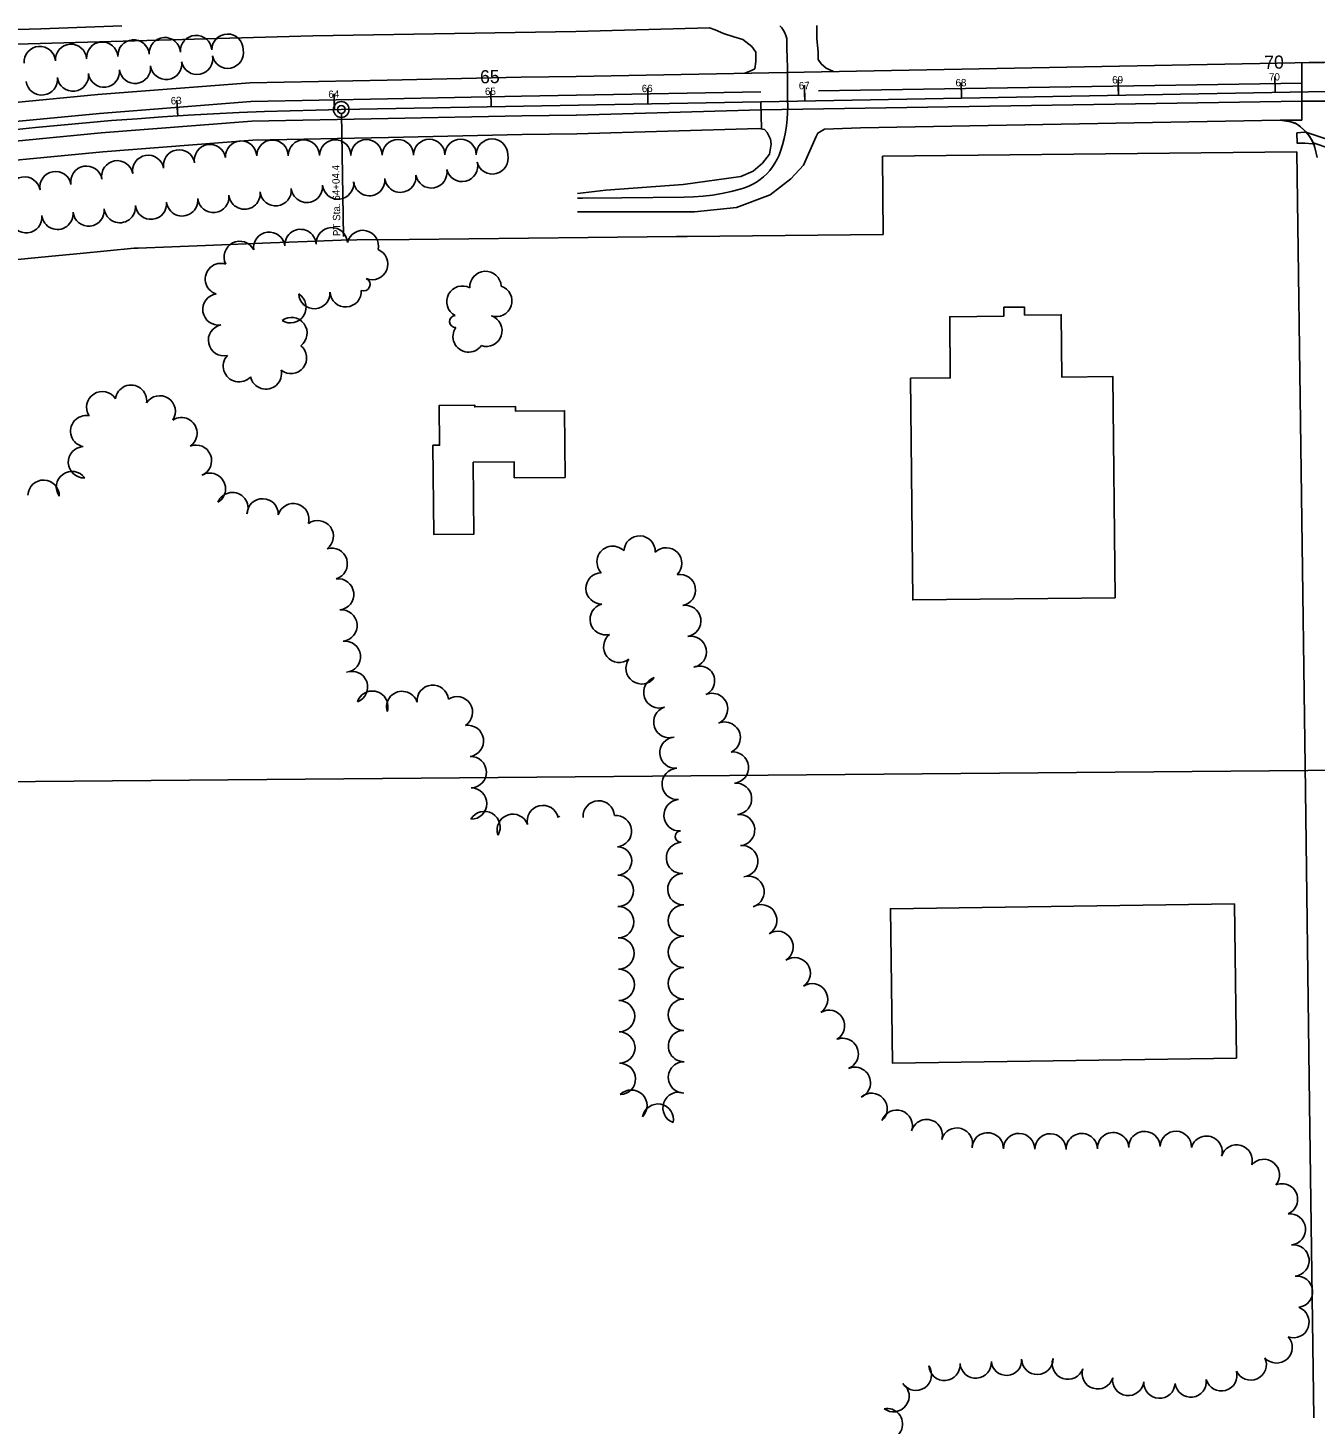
# Model space of a CAD drawing. Extents: x -2233 to 187241, y 4582 to 150524.
# Drawn here: x 106148 to 106969, y 58600 to 59491 of the extents above; entities that cross this region are included whole.
import ezdxf

# ---------------------------------------------------------------- set-up
doc = ezdxf.new("R2010")
doc.units = 0
for name, color, linetype in [('AP_X_Misc', 7, 'Continuous'), ('BLDG', 7, 'Continuous'), ('GE_X_CL_100', 7, 'Continuous'), ('GE_X_CL_20', 7, 'Continuous'), ('GE_X_CL_2000', 7, 'Continuous'), ('GE_X_CL_50', 7, 'Continuous'), ('GRID', 7, 'Continuous'), ('PM_P_CL_Double_Solid', 7, 'Continuous'), ('PM_P_Crosswalk', 7, 'Continuous'), ('PM_P_Edge_Line', 7, 'Continuous'), ('PM_P_Lane_Line', 7, 'Continuous'), ('PM_P_Text', 7, 'Continuous'), ('PV_P_Curb_Ramp', 7, 'Continuous'), ('ROAD', 7, 'Continuous'), ('RW_X_Fee_RW', 7, 'Continuous'), ('SC_Scratch2', 7, 'Continuous'), ('TREES', 7, 'Continuous')]:
    doc.layers.add(name, color=color, linetype=linetype)

msp = doc.modelspace()

# ---------------------------------------------------------------- linework, layer by layer
at = {"layer": 'AP_X_Misc'}
for p, q in [((106960.12, 59431.73), (106960.11, 59468.34)), ((106946.44, 59431.71), (106960.12, 59431.73))]:
    msp.add_line(p, q, dxfattribs=at)
at = {"layer": 'BLDG'}
for points in [[(106841.13, 59127.15), (106839.71, 59268.23), (106807.13, 59267.9), (106806.73, 59307.67), (106783.38, 59307.43), (106783.32, 59312.55), (106770.16, 59312.42), (106770.22, 59306.75), (106735.64, 59306.4), (106736.03, 59267.4), (106710.64, 59267.14), (106712.07, 59125.86)], [(106457.94, 59203.65), (106457.85, 59213.86), (106431.86, 59213.63), (106432.26, 59167.76), (106406.63, 59167.53), (106406.14, 59224.38), (106410.39, 59224.42), (106410.16, 59249.8), (106432.8, 59249.99), (106432.81, 59248.83), (106458.69, 59249.06), (106458.72, 59246.21), (106490.02, 59246.48), (106490.39, 59203.93)], [(106918.55, 58833.53), (106699.14, 58830.47), (106697.78, 58928.9), (106917.18, 58931.96)]]:
    msp.add_lwpolyline(points, close=True, dxfattribs=at)
at = {"layer": 'GE_X_CL_100'}
for p, q in [((106843.19, 59447.64), (106843.01, 59457.64)), ((106943.17, 59449.48), (106942.99, 59459.48)), ((106343.27, 59438.43), (106343.09, 59448.43)), ((106443.26, 59440.27), (106443.07, 59450.27)), ((106543.24, 59442.11), (106543.06, 59452.11)), ((106643.22, 59443.95), (106643.04, 59453.95)), ((106743.21, 59445.8), (106743.02, 59455.79)), ((106243.36, 59434.39), (106242.74, 59444.38))]:
    msp.add_line(p, q, dxfattribs=at)
msp.add_circle((106347.67, 59438.51), 5, dxfattribs=at)
at = {"layer": 'GE_X_CL_20'}
msp.add_line((106347.67, 59438.51), (106987.56, 59450.3), dxfattribs=at)
msp.add_arc((106385.76, 57147), 2291.83, 90.95239, 116.95239, dxfattribs=at)
at = {"layer": 'GE_X_CL_2000'}
msp.add_line((106347.67, 59438.51), (106987.56, 59450.3), dxfattribs=at)
for points in [[(106103.58, 59488.39), (106156.07, 59489.9), (106207.73, 59491.9)], [(106627.25, 59491.87), (106628.51, 59490.49), (106629.59, 59488.97), (106630.48, 59487.34), (106631.19, 59485.61), (106631.68, 59483.81), (106631.84, 59477.6), (106632.05, 59471.36), (106632.29, 59465.1), (106632.15, 59444.74)], [(106498.36, 59382.03), (106501.38, 59382.08), (106526.62, 59382.27), (106566.24, 59382.57), (106572.3, 59382.77), (106578.34, 59383.23), (106584.35, 59383.96), (106590.33, 59384.93), (106596.25, 59386.17), (106602.12, 59387.66), (106604.82, 59388.51), (106607.45, 59389.56), (106610, 59390.81), (106612.44, 59392.24), (106614.76, 59393.86), (106616.96, 59395.64), (106619.02, 59397.59), (106620.92, 59399.69), (106622.66, 59401.92), (106624.23, 59404.28), (106625.61, 59406.75), (106626.81, 59409.32), (106627.8, 59411.97), (106629.06, 59415.93), (106630.12, 59419.95), (106630.98, 59424.02), (106631.63, 59428.13), (106632.07, 59432.27), (106632.31, 59436.42), (106632.34, 59440.58), (106632.15, 59444.74)]]:
    msp.add_lwpolyline(points, dxfattribs=at)
msp.add_arc((106385.76, 57147), 2291.83, 90.95239, 116.95239, dxfattribs=at)
at = {"layer": 'GE_X_CL_50'}
for p, q in [((106643.22, 59443.95), (106643.13, 59448.95)), ((106743.21, 59445.8), (106743.11, 59450.79)), ((106843.19, 59447.64), (106843.1, 59452.64)), ((106943.17, 59449.48), (106943.08, 59454.48)), ((106243.36, 59434.39), (106243.05, 59439.39)), ((106343.27, 59438.43), (106343.18, 59443.43)), ((106443.26, 59440.27), (106443.17, 59445.27)), ((106543.24, 59442.11), (106543.15, 59447.11)), ((106347.71, 59436.01), (106349.01, 59357.59))]:
    msp.add_line(p, q, dxfattribs=at)
msp.add_circle((106347.67, 59438.51), 2.5, dxfattribs=at)
at = {"layer": 'GRID'}
msp.add_line((109999.81, 59043.63), (105000, 59000), dxfattribs=at)
at = {"layer": 'PM_P_CL_Double_Solid'}
for points in [[(106615.11, 59449.78), (106497.74, 59447.55)], [(106960.11, 59455.36), (106651.98, 59450.48)]]:
    msp.add_lwpolyline(points, dxfattribs=at)
at = {"layer": 'PM_P_Crosswalk'}
for p, q in [((106963.43, 59423.89), (107002.44, 59410.71)), ((106967.45, 59417.25), (106998.78, 59406.67))]:
    msp.add_line(p, q, dxfattribs=at)
at = {"layer": 'PM_P_Edge_Line'}
msp.add_line((107365.13, 59472.28), (106960.11, 59468.34), dxfattribs=at)
at = {"layer": 'PM_P_Lane_Line'}
msp.add_line((106615.32, 59438.39), (106960.1, 59443.73), dxfattribs=at)
msp.add_lwpolyline([(106497.51, 59434.97), (106615.32, 59438.39)], dxfattribs=at)
at = {"layer": 'PM_P_Text'}
for p, q in [((106960.11, 59468.34), (106960.11, 59449.79)), ((106615.55, 59426.09), (106615.23, 59443.44)), ((107174.27, 59443.73), (106960.1, 59443.73))]:
    msp.add_line(p, q, dxfattribs=at)
msp.add_lwpolyline([(106978.3, 59468.68), (106964.89, 59468.43), (106960.11, 59468.34), (106960.12, 59431.73), (106947.63, 59431.71), (106947.97, 59431.5), (106952.36, 59430.88), (106956.8, 59429.32), (106959.33, 59427.47), (106962.31, 59424.71), (106965, 59421.5), (106967.45, 59417.25), (106968.43, 59414.36), (106969.96, 59407.97)], dxfattribs=at)
at = {"layer": 'PV_P_Curb_Ramp'}
msp.add_lwpolyline([(106962.49, 59424.54), (106962.07, 59424.11), (106957.04, 59423.55), (106957.12, 59417.05), (106962.12, 59417.11), (106967, 59416.67), (106967.46, 59416.87), (106967.57, 59416.91), (106967.39, 59417.37), (106967.1, 59417.96), (106966.75, 59418.65), (106966.34, 59419.46), (106965.8, 59420.28), (106965.27, 59421.09), (106964.79, 59421.82), (106964.27, 59422.53), (106963.7, 59423.33), (106963.11, 59423.94), (106962.7, 59424.34)], close=True, dxfattribs=at)
at = {"layer": 'ROAD'}
for p, q in [((106582.43, 59490.51), (106497.26, 59488.33)), ((106586, 59489.21), (106582.43, 59490.51)), ((106591.34, 59487.04), (106586, 59489.21)), ((106598.07, 59484.86), (106591.34, 59487.04)), ((106603.8, 59483.08), (106598.07, 59484.86)), ((106650.87, 59483.87), (106650.87, 59491.98)), ((106651.66, 59474.96), (106650.87, 59483.87)), ((106609.54, 59478.72), (106603.8, 59483.08)), ((106611.91, 59474.96), (106609.54, 59478.72)), ((106612.11, 59469.03), (106611.91, 59474.96)), ((106651.86, 59470.41), (106651.66, 59474.96)), ((106611.32, 59464.47), (106612.11, 59469.03)), ((106653.64, 59467.64), (106651.86, 59470.41)), ((106656.8, 59464.87), (106653.64, 59467.64)), ((106605, 59461.59), (106609.34, 59463.29)), ((106609.34, 59463.29), (106611.32, 59464.47)), ((106661.54, 59462.66), (106656.8, 59464.87)), ((106953.21, 59430.75), (106956.18, 59429.71)), ((106956.18, 59429.71), (106958.59, 59428.15)), ((106958.59, 59428.15), (106961.35, 59425.63)), ((106961.35, 59425.63), (106963.87, 59423.23)), ((106963.87, 59423.23), (106966.39, 59419.38)), ((106966.39, 59419.38), (106968.07, 59416.02)), ((106968.07, 59416.02), (106969.03, 59411.57))]:
    msp.add_line(p, q, dxfattribs=at)
for points in [[(106497.26, 59488.33), (106329.48, 59485.47), (106079.75, 59478.46), (105931.93, 59468.28), (105826.01, 59457.32), (105721.13, 59446), (105603.24, 59445.25), (105485.35, 59444.84), (105434.18, 59444.31), (105434.13, 59456.85), (105486.04, 59457.57)], [(106987.22, 59468.85), (106978.05, 59468.68), (106497.52, 59459.55)], [(104999.7, 59034.53), (105190.49, 59131.84), (105403.11, 59236.78), (105494.31, 59278.2), (105553.54, 59301.72), (105609.36, 59322.45), (105659.05, 59340.78), (105713.68, 59357.33), (105772.85, 59375.01), (105832.32, 59390.92), (105892.41, 59404.68), (105978.56, 59422.58), (106062.47, 59435.45), (106192.37, 59448), (106289.41, 59455.59), (106376.98, 59457.23), (106462.38, 59459.08), (106497.52, 59459.55)], [(106498.31, 59373.33), (106572.91, 59373.2), (106599.64, 59376.04), (106621.18, 59384.17), (106634.3, 59394.31), (106642.45, 59403.01), (106650.55, 59421.19), (106651.32, 59423.01), (106651.47, 59423.45), (106655.85, 59426.03), (106678.84, 59426.88), (106946.44, 59431.71), (106953.21, 59430.75)], [(105000.06, 58993.66), (105206.89, 59099.15), (105418.77, 59203.72), (105508.63, 59244.54), (105566.66, 59267.58), (105622.05, 59288.16), (105670.69, 59306.09), (105724.21, 59322.31), (105782.81, 59339.82), (105841.13, 59355.41), (105900.21, 59368.96), (105985.06, 59386.57), (106067.01, 59399.15), (106195.54, 59411.58), (106291.18, 59419.04), (106377.73, 59420.68), (106463.02, 59422.52), (106497.86, 59422.98)], [(106497.86, 59422.98), (106613.89, 59426.34), (106617.44, 59425.8), (106619.19, 59423.94), (106621.34, 59419.55), (106621.82, 59416.45), (106620.66, 59410), (106616.31, 59404.3), (106610.23, 59399.1), (106602.53, 59395.75), (106565.76, 59390.69), (106516.33, 59387.16), (106498.21, 59384.98)]]:
    msp.add_lwpolyline(points, dxfattribs=at)
at = {"layer": 'RW_X_Fee_RW'}
for p, q in [((106692.68, 59408.83), (106956.9, 59411.59)), ((106693.2, 59358.83), (106692.68, 59408.83))]:
    msp.add_line(p, q, dxfattribs=at)
for points in [[(106956.9, 59411.59), (106962.45, 59004.32), (106965.17, 58804.34), (106967.9, 58604.35)], [(106347.6, 59355.22), (106357.59, 59355.33), (106390.98, 59355.68), (106505.2, 59356.87), (106561.39, 59357.46), (106568.2, 59357.53), (106693.2, 59358.83)], [(106003.93, 59324.76), (106053.82, 59332.53), (106061.34, 59333.71), (106084.09, 59337.25), (106167.62, 59345.37), (106181.1, 59346.68), (106198.35, 59348.36), (106215.59, 59350.04), (106218.06, 59350.13), (106261.04, 59351.82), (106302.52, 59353.45), (106326, 59354.37), (106347.6, 59355.22)]]:
    msp.add_lwpolyline(points, dxfattribs=at)
at = {"layer": 'SC_Scratch2'}
for points in [[(105005.15, 59023.84), (105195.87, 59121.11), (105408.25, 59225.93), (105499.01, 59267.16), (105557.84, 59290.52), (105613.52, 59311.2), (105662.87, 59329.4), (105717.14, 59345.84), (105776.12, 59363.46), (105835.21, 59379.27), (105894.97, 59392.96), (105980.69, 59410.76), (106063.96, 59423.54), (106193.41, 59436.05), (106289.99, 59443.6), (106377.22, 59445.24), (106462.59, 59447.08), (106497.68, 59447.55)], [(104982.66, 58998.26), (105201.51, 59109.88), (105413.63, 59214.57), (105503.93, 59255.58), (105562.35, 59278.78), (105617.88, 59299.41), (105666.88, 59317.48), (105720.76, 59333.8), (105779.55, 59351.37), (105838.24, 59367.06), (105897.65, 59380.68), (105982.93, 59398.38), (106065.52, 59411.06), (106194.5, 59423.53), (106290.6, 59431.03), (106377.49, 59432.68), (106462.81, 59434.52), (106497.7, 59434.98)]]:
    msp.add_lwpolyline(points, dxfattribs=at)
at = {"layer": 'TREES'}
for centre, radius, start, end in [((106235.18, 59474.4), 10, 4.05466, 184.05466), ((106255.13, 59475.81), 10, 4.05466, 184.05466), ((106275.1, 59476.62), 10, 0.60364, 180.60364), ((106155.38, 59468.74), 10, 4.05466, 184.05466), ((106175.33, 59470.15), 10, 4.05466, 184.05466), ((106195.28, 59471.57), 10, 4.05466, 184.05466), ((106215.23, 59472.98), 10, 4.05466, 184.05466), ((106275.3, 59474.75), 10, 191.40576, 11.40576), ((106216.12, 59465.11), 10, 187.12499, 7.12499), ((106235.97, 59467.59), 10, 187.12499, 7.12499), ((106255.69, 59470.8), 10, 191.38183, 11.38183), ((106156.69, 59457.68), 10, 187.12499, 7.12499), ((106176.54, 59460.16), 10, 187.12499, 7.12499), ((106196.33, 59462.63), 9.94, 187.12499, 7.12499), ((106244.25, 59402.8), 10, 9.94353, 189.94353), ((106263.95, 59406.26), 10, 9.94353, 189.94353), ((106283.79, 59408.48), 10, 2.83434, 182.83434), ((106303.78, 59409.02), 10, 0.27685, 180.27685), ((106323.78, 59409.12), 10, 0.27685, 180.27685), ((106343.78, 59409.21), 10, 0.27685, 180.27685), ((106363.78, 59409.31), 10, 0.27685, 180.27685), ((106383.78, 59409.41), 10, 0.27685, 180.27685), ((106403.78, 59409.5), 10, 0.27685, 180.27685), ((106423.78, 59409.6), 10, 0.27685, 180.27685), ((106443.78, 59409.7), 10, 0.27685, 180.27685), ((106204.85, 59395.9), 10, 9.94353, 189.94353), ((106224.55, 59399.35), 10, 9.94353, 189.94353), ((106424.65, 59402.55), 10, 193.87455, 13.87455), ((106444.07, 59407.35), 10, 193.89153, 13.89153), ((106145.76, 59385.54), 10, 9.94353, 189.94353), ((106165.45, 59388.99), 10, 9.94353, 189.94353), ((106185.15, 59392.44), 10, 9.94353, 189.94353), ((106365.5, 59393.49), 10, 186.17001, 6.17001), ((106385.34, 59395.63), 9.96, 186.17001, 6.17001), ((106405.09, 59398.42), 10, 189.92523, 9.92523), ((106285.97, 59384.89), 10, 186.17001, 6.17001), ((106305.85, 59387.04), 10, 186.17002, 6.17002), ((106325.74, 59389.19), 10, 186.17001, 6.17001), ((106345.62, 59391.34), 10, 186.17002, 6.17002), ((106206.43, 59376.29), 10, 186.17001, 6.17001), ((106226.31, 59378.44), 10, 186.17002, 6.17002), ((106246.2, 59380.59), 10, 186.17001, 6.17001), ((106266.08, 59382.74), 10, 186.17002, 6.17002), ((106146.78, 59369.84), 10, 186.17002, 6.17002), ((106166.66, 59371.99), 10, 186.17001, 6.17001), ((106186.55, 59374.14), 10, 186.17002, 6.17002), ((106301.75, 59350.32), 10, 7.13214, 187.13214), ((106321.66, 59352.12), 10, 3.17474, 183.17474), ((106341.63, 59353.22), 10, 3.10689, 183.10689), ((106361.35, 59351.48), 10, 346.85582, 166.85582), ((106282.93, 59344.51), 10, 27.23761, 207.23761), ((106367.35, 59339.94), 10, 248.03925, 68.03925), ((106270.93, 59330.43), 10, 71.83967, 251.83967), ((106439.64, 59325.36), 10, 3.16185, 183.16185), ((106350.46, 59322.63), 10, 183.22099, 3.22099), ((106362.02, 59326.92), 4.06, 247.03324, 67.03324), ((106424.95, 59315.99), 10, 61.92291, 241.92291), ((106446.54, 59316.4), 10, 252.0162, 72.0162), ((106269.31, 59311.04), 10, 98.60782, 278.60782), ((106315.21, 59312.46), 10, 238.0388, 58.0388), ((106330.49, 59321.5), 10, 183.22099, 3.22099), ((106315.88, 59295.94), 10, 306.61412, 126.61412), ((106420.49, 59303.38), 3.79, 93.6986, 273.6986), ((106440.22, 59297.42), 10, 251.18797, 71.18797), ((106272.91, 59291.38), 10, 102.18291, 282.18291), ((106428.87, 59293.78), 10, 144.43434, 324.43434), ((106315.6, 59280.1), 10, 231.38698, 51.38698), ((106282.41, 59274.86), 10, 137.63894, 317.63894), ((106299.58, 59270.21), 10, 192.02005, 12.02006), ((106213.59, 59252.79), 10, 352.56159, 172.5616), ((106195.27, 59248.67), 10, 32.76583, 212.76583), ((106231.87, 59246), 10, 326.70624, 146.70624), ((106185.02, 59233.43), 10, 79.36759, 259.36759), ((106245.73, 59232.16), 10, 303.3906, 123.3906), ((106183.61, 59213.61), 10, 92.50996, 272.50996), ((106254.99, 59214.55), 10, 292.0853, 112.0853), ((106175.94, 59197.76), 10, 35.86219, 215.86219), ((106157.84, 59192.27), 10, 357.92135, 177.92135), ((106263.85, 59196.68), 10, 300.6556, 120.6556), ((106278.23, 59184.36), 10, 338.15464, 158.15464), ((106297.51, 59180.36), 10, 358.40137, 178.40137), ((106317.11, 59177.27), 10, 343.68028, 163.68028), ((106332.68, 59166.44), 10, 306.70408, 126.70408), ((106537.89, 59156.65), 10, 357.77698, 177.77698), ((106341.56, 59148.85), 10, 286.8767, 106.8767), ((106520.68, 59150.11), 10, 43.83704, 223.83705), ((106554.85, 59149.09), 10, 314.16257, 134.16257), ((106345.65, 59129.35), 10, 276.80588, 96.80588), ((106513.67, 59133.19), 10, 91.14389, 271.14389), ((106563.59, 59132.08), 10, 280.22505, 100.22505), ((106347.8, 59109.47), 10, 275.57965, 95.57965), ((106516.32, 59113.5), 10, 104.16227, 284.16227), ((106566.99, 59112.37), 10, 279.35158, 99.35158), ((106524.93, 59095.93), 10, 128.04871, 308.04871), ((106570.5, 59092.68), 10, 280.87482, 100.87482), ((106349.9, 59089.58), 10, 276.46839, 96.46839), ((106539.18, 59082.17), 10, 143.99609, 323.99609), ((106576.22, 59074.15), 9.52, 293.77626, 113.77626), ((106354.49, 59070.27), 10, 290.24859, 110.24859), ((106550.48, 59066.83), 10, 108.76421, 288.76421), ((106367.45, 59057.74), 10, 341.69327, 161.69327), ((106386.49, 59057.56), 10, 17.21357, 197.21357), ((106405.99, 59061.52), 10, 5.75859, 185.75859), ((106584.09, 59056.29), 10, 293.77626, 113.77626), ((106421.39, 59054.14), 10, 302.99496, 122.99496), ((106556.85, 59047.87), 10, 108.36645, 288.36645), ((106592.16, 59037.99), 10, 293.77626, 113.77626), ((106428.37, 59035.87), 10, 278.84258, 98.84258), ((106560.81, 59028.41), 10, 94.64427, 274.64427), ((106430.22, 59015.99), 10, 271.77439, 91.77439), ((106597.31, 59018.9), 10, 276.43462, 96.43462), ((106562.21, 59008.46), 10, 93.35089, 273.35089), ((106430.43, 58996), 10, 269.44524, 89.44524), ((106599.39, 58999.01), 10, 275.53365, 95.53365), ((106476.21, 58984.84), 10, 13.36522, 193.36522), ((106511.84, 58987.74), 10, 3.25099, 183.25099), ((106563.38, 58988.49), 10, 93.35089, 273.35089), ((106438.97, 58980.96), 10, 329.71942, 149.71942), ((106457.04, 58979.22), 10, 19.29985, 199.29985), ((106486.36, 58987.25), 0.431, 12.98635, 192.98635), ((106522.78, 58978.35), 10, 275.5119, 95.5119), ((106601.32, 58979.1), 10, 275.53365, 95.53365), ((106564.17, 58974.91), 3.61, 93.35088, 273.35088), ((106523.83, 58959.38), 9.02, 270.54856, 90.54856), ((106564.94, 58961.33), 10, 93.17633, 273.17633), ((106603.32, 58959.2), 10, 275.91287, 95.91287), ((106524.01, 58940.36), 10, 270.54856, 90.54856), ((106565.81, 58941.35), 10, 91.84251, 271.84251), ((106607.31, 58939.71), 10, 287.22339, 107.22339), ((106615.41, 58921.58), 10, 300.96777, 120.96777), ((106524.21, 58920.36), 10, 270.54856, 90.54856), ((106566.14, 58921.35), 10, 90.02733, 270.02733), ((106625.9, 58904.55), 10, 302.27751, 122.27751), ((106524.4, 58900.36), 10, 270.54856, 90.54856), ((106566.15, 58901.35), 10, 90.02733, 270.02733), ((106636.8, 58887.78), 10, 303.74679, 123.74679), ((106524.59, 58880.36), 10, 270.54856, 90.54856), ((106566.16, 58881.35), 10, 90.02733, 270.02733), ((106647.91, 58871.15), 10, 303.74679, 123.74679), ((106524.78, 58860.36), 10, 270.54856, 90.54856), ((106566.18, 58861.35), 10, 90.09614, 270.09614), ((106658.58, 58854.24), 10, 300.76712, 120.76712), ((106566.23, 58841.35), 10, 90.2239, 270.2239), ((106524.97, 58840.37), 10, 270.54856, 90.54856), ((106667.38, 58836.36), 10, 291.65986, 111.65986), ((106525.3, 58820.37), 10, 271.32165, 91.32165), ((106566.21, 58821.35), 10, 89.62543, 269.62543), ((106675.13, 58817.92), 10, 293.95642, 113.95642), ((106532.63, 58803.33), 10, 315.25272, 135.25272), ((106562.76, 58801.94), 10, 70.22321, 250.22321), ((106685.82, 58801.3), 10, 311.49616, 131.49616), ((106549.55, 58794.41), 10, 349.16599, 169.16599), ((106701.9, 58790.54), 10, 340.92701, 160.92701), ((106720.97, 58784.56), 10, 344.27509, 164.27509), ((106740.23, 58779.14), 10, 344.2751, 164.2751), ((106759.85, 58776.12), 10, 358.24474, 178.24474), ((106779.84, 58775.7), 10, 359.34978, 179.34978), ((106799.84, 58775.48), 10, 359.34978, 179.34978), ((106819.84, 58775.62), 10, 1.44881, 181.44881), ((106839.83, 58776.23), 10, 2.04982, 182.04982), ((106859.81, 58776.94), 10, 2.04982, 182.04982), ((106879.8, 58777.03), 10, 358.43587, 178.43587), ((106899.41, 58773.98), 10, 343.88937, 163.88937), ((106918.6, 58768.36), 10, 343.47844, 163.47844), ((106935.92, 58759.17), 10, 320.59503, 140.59503), ((106947.5, 58743.6), 10, 292.71236, 112.71236), ((106952.51, 58724.44), 10, 276.60716, 96.60716), ((106954.82, 58704.57), 10, 276.61478, 96.61478), ((106957.08, 58684.7), 10, 276.35216, 96.35216), ((106954.83, 58665.34), 10, 250.42196, 70.42196), ((106944.06, 58649.21), 10, 222.13244, 42.13244), ((106732.29, 58638.11), 10, 184.21062, 4.21062), ((106752.24, 58639.58), 10, 184.21062, 4.21062), ((106771.86, 58641.03), 9.68, 184.21062, 4.21062), ((106791.51, 58641.89), 10, 180.8591, 0.8591), ((106810.98, 58638.83), 10, 161.30032, 341.30032), ((106927.56, 58638.33), 10, 204.64113, 24.64112), ((106714.06, 58631.74), 10, 214.33007, 34.33007), ((106830.01, 58632.67), 10, 162.83347, 342.83347), ((106849.48, 58628.47), 10, 172.77376, 352.77376), ((106908.85, 58631.42), 10, 195.89164, 15.89164), ((106699.78, 58618.12), 10, 232.94752, 52.94752), ((106869.39, 58626.73), 10, 177.27319, 357.27319), ((106889.31, 58627.47), 10, 186.97235, 6.97235), ((106695.6, 58600.31), 10, 280.61472, 100.61472)]:
    msp.add_arc(centre, radius, start, end, dxfattribs=at)

# ---------------------------------------------------------------- texts
at = {"layer": 'GE_X_CL_100'}
for s, p in [('70', (106936.27, 59464.36)), ('65', (106436.23, 59455.14))]:
    msp.add_text(s, height=8.4, rotation=1.05577, dxfattribs=at).set_placement(p)
at = {"layer": 'GE_X_CL_50'}
for s, rotation, p in [('68', 1.05577, (106739.38, 59453.23)), ('69', 1.05577, (106839.28, 59455.07)), ('70', 1.05577, (106939.3, 59456.91)), ('64', 1.06217, (106339.45, 59445.86)), ('65', 1.05577, (106439.33, 59447.7)), ('66', 1.05577, (106539.32, 59449.54)), ('67', 1.05577, (106639.44, 59451.38)), ('63', 3.56218, (106239.07, 59441.64)), ('PT Sta. 64+04.4', 90.95239, (106347.18, 59357.81))]:
    msp.add_text(s, height=4.68, rotation=rotation, dxfattribs=at).set_placement(p)

doc.saveas('drawing.dxf')
